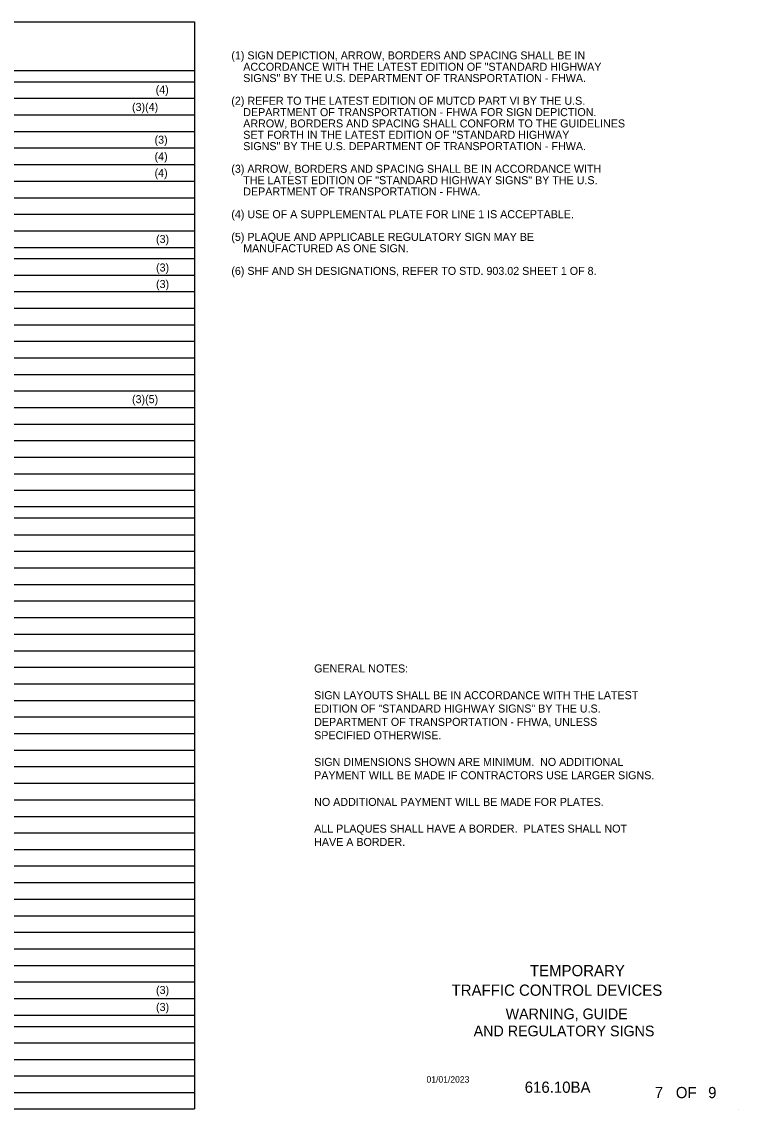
# Model space of a CAD drawing. Extents: x -439.1 to -407.9, y -458.1 to -437.7.
# Drawn here: x -421.29 to -407.86, y -458.05 to -437.68 of the extents above; entities that cross this region are included whole.
import ezdxf

# ---------------------------------------------------------------- set-up
doc = ezdxf.new("R2010")
doc.units = 0
for name, color, linetype in [('Common-Notes', 7, 'Continuous'), ('Level 4', 7, 'Continuous'), ('Level 45', 7, 'Continuous')]:
    doc.layers.add(name, color=color, linetype=linetype)

msp = doc.modelspace()

# ---------------------------------------------------------------- linework, layer by layer
at = {"layer": 'Common-Notes'}
msp.add_line((-439.109, -445.834), (-418.049, -445.834), dxfattribs=at)
at = {"layer": 'Level 4'}
for p, q in [((-439.109, -437.676), (-418.049, -437.676)), ((-418.049, -437.676), (-418.049, -458.044)), ((-439.109, -438.59), (-418.049, -438.59)), ((-439.109, -438.8), (-418.049, -438.8)), ((-439.109, -439.11), (-418.049, -439.11)), ((-439.109, -439.421), (-418.049, -439.421)), ((-439.109, -439.731), (-418.049, -439.731)), ((-439.109, -440.041), (-418.049, -440.041)), ((-439.109, -440.351), (-418.049, -440.351)), ((-439.109, -440.662), (-418.049, -440.662)), ((-439.109, -440.972), (-418.049, -440.972)), ((-439.109, -441.282), (-418.049, -441.282)), ((-439.109, -441.593), (-418.049, -441.593)), ((-439.109, -441.903), (-418.049, -441.903)), ((-439.109, -442.11), (-418.049, -442.11)), ((-439.109, -442.421), (-418.049, -442.421)), ((-439.109, -442.731), (-418.049, -442.731)), ((-439.109, -443.041), (-418.049, -443.041)), ((-439.109, -443.352), (-418.049, -443.352)), ((-439.109, -443.662), (-418.049, -443.662)), ((-439.109, -443.972), (-418.049, -443.972)), ((-439.109, -444.283), (-418.049, -444.283)), ((-439.109, -444.593), (-418.049, -444.593)), ((-439.109, -444.903), (-418.049, -444.903)), ((-418.762, -444.903), (-418.763, -444.903)), ((-439.109, -445.214), (-418.049, -445.214)), ((-439.109, -445.524), (-418.049, -445.524)), ((-439.109, -446.145), (-418.049, -446.145)), ((-439.109, -446.455), (-418.049, -446.455)), ((-418.049, -446.765), (-439.109, -446.765)), ((-418.049, -446.977), (-439.109, -446.977)), ((-439.109, -447.287), (-418.049, -447.287)), ((-439.109, -447.597), (-418.049, -447.597)), ((-439.109, -447.908), (-418.049, -447.908)), ((-439.109, -448.218), (-418.049, -448.218)), ((-439.109, -448.528), (-418.049, -448.528)), ((-439.109, -448.839), (-418.049, -448.839)), ((-439.109, -449.149), (-418.049, -449.149)), ((-439.109, -449.459), (-418.049, -449.459)), ((-439.109, -449.77), (-418.049, -449.77)), ((-439.109, -450.08), (-418.049, -450.08)), ((-439.109, -450.39), (-418.049, -450.39)), ((-439.109, -450.701), (-418.049, -450.701)), ((-439.109, -451.011), (-418.049, -451.011)), ((-439.109, -451.321), (-418.049, -451.321)), ((-439.109, -451.632), (-418.049, -451.632)), ((-439.109, -451.942), (-418.049, -451.942)), ((-439.109, -452.252), (-418.049, -452.252)), ((-439.109, -452.563), (-418.049, -452.563)), ((-439.109, -452.873), (-418.049, -452.873)), ((-439.109, -453.183), (-418.049, -453.183)), ((-439.109, -453.493), (-418.049, -453.493)), ((-439.109, -453.804), (-418.049, -453.804)), ((-439.109, -454.114), (-418.049, -454.114)), ((-439.109, -454.424), (-418.049, -454.424)), ((-439.109, -454.735), (-418.049, -454.735)), ((-439.109, -455.045), (-418.049, -455.045)), ((-439.109, -455.355), (-418.049, -455.355)), ((-439.109, -455.666), (-418.049, -455.666)), ((-439.109, -455.976), (-418.049, -455.976)), ((-439.109, -456.286), (-418.049, -456.286)), ((-439.109, -456.498), (-418.049, -456.498)), ((-439.109, -456.808), (-418.049, -456.808)), ((-439.109, -457.118), (-418.049, -457.118)), ((-439.109, -457.424), (-418.049, -457.424)), ((-439.109, -457.735), (-418.049, -457.735)), ((-439.109, -458.044), (-418.049, -458.044)), ((-407.859, -458.051), (-407.859, -458.051))]:
    msp.add_line(p, q, dxfattribs=at)

# ---------------------------------------------------------------- texts
at = {"layer": 'Common-Notes'}
for s, p in [('TEMPORARY', (-411.763, -455.558)), ('TRAFFIC CONTROL DEVICES', (-413.231, -455.925)), ('616.10BA', (-411.861, -457.743)), ('7', (-409.424, -457.843)), ('OF', (-409.029, -457.843)), ('9', (-408.424, -457.843))]:
    msp.add_text(s, height=0.21, dxfattribs=at).set_placement(p)
at = {"layer": 'Level 4'}
for s, height, p in [('(1) SIGN DEPICTION, ARROW, BORDERS AND SPACING SHALL BE IN ', 0.15, (-417.359, -438.381)), ('    ACCORDANCE WITH THE LATEST EDITION OF "STANDARD HIGHWAY ', 0.15, (-417.359, -438.594)), ('    SIGNS" BY THE U.S. DEPARTMENT OF TRANSPORTATION - FHWA.', 0.15, (-417.359, -438.806)), ('(4)', 0.15, (-418.777, -439.021)), ('(2) REFER TO THE LATEST EDITION OF MUTCD PART VI BY THE U.S. ', 0.15, (-417.359, -439.231)), ('(3)(4)', 0.15, (-419.22, -439.347)), ('    DEPARTMENT OF TRANSPORTATION - FHWA FOR SIGN DEPICTION. ', 0.15, (-417.359, -439.444)), ('    ARROW, BORDERS AND SPACING SHALL CONFORM TO THE GUIDELINES ', 0.15, (-417.359, -439.656)), ('(3)', 0.15, (-418.798, -439.961)), ('    SET FORTH IN THE LATEST EDITION OF "STANDARD HIGHWAY ', 0.15, (-417.359, -439.869)), ('    SIGNS" BY THE U.S. DEPARTMENT OF TRANSPORTATION - FHWA.', 0.15, (-417.359, -440.081)), ('(4)', 0.15, (-418.798, -440.272)), ('(4)', 0.15, (-418.798, -440.582)), ('(3) ARROW, BORDERS AND SPACING SHALL BE IN ACCORDANCE WITH ', 0.15, (-417.359, -440.506)), ('    THE LATEST EDITION OF "STANDARD HIGHWAY SIGNS" BY THE U.S. ', 0.15, (-417.359, -440.719)), ('    DEPARTMENT OF TRANSPORTATION - FHWA.', 0.15, (-417.359, -440.931)), ('(4) USE OF A SUPPLEMENTAL PLATE FOR LINE 1 IS ACCEPTABLE.', 0.15, (-417.359, -441.356)), ('(3)', 0.15, (-418.77, -441.821)), ('(5) PLAQUE AND APPLICABLE REGULATORY SIGN MAY BE ', 0.15, (-417.359, -441.781)), ('    MANUFACTURED AS ONE SIGN.', 0.15, (-417.359, -441.994)), ('(3)', 0.15, (-418.77, -442.355)), ('(6) SHF AND SH DESIGNATIONS, REFER TO STD. 903.02 SHEET 1 OF 8.', 0.15, (-417.359, -442.419)), ('(3)', 0.15, (-418.77, -442.665)), ('(3)(5)', 0.15, (-419.22, -444.822)), ('(3)', 0.15, (-418.77, -455.891)), ('(3)', 0.15, (-418.77, -456.209)), ('WARNING, GUIDE', 0.2, (-412.218, -456.364)), ('AND REGULATORY SIGNS', 0.2, (-412.818, -456.684)), ('01/01/2023', 0.12, (-413.701, -457.552))]:
    msp.add_text(s, height=height, dxfattribs=at).set_placement(p)
at = {"layer": 'Level 45'}
for s, p in [('GENERAL NOTES:', (-415.807, -449.868)), ('SIGN LAYOUTS SHALL BE IN ACCORDANCE WITH THE LATEST ', (-415.807, -450.368)), ('EDITION OF "STANDARD HIGHWAY SIGNS" BY THE U.S. ', (-415.807, -450.618)), ('DEPARTMENT OF TRANSPORTATION - FHWA, UNLESS ', (-415.807, -450.868)), ('SPECIFIED OTHERWISE.', (-415.807, -451.118)), ('SIGN DIMENSIONS SHOWN ARE MINIMUM.  NO ADDITIONAL ', (-415.807, -451.618)), ('PAYMENT WILL BE MADE IF CONTRACTORS USE LARGER SIGNS.', (-415.807, -451.868)), ('NO ADDITIONAL PAYMENT WILL BE MADE FOR PLATES. ', (-415.807, -452.368)), ('ALL PLAQUES SHALL HAVE A BORDER.  PLATES SHALL NOT ', (-415.807, -452.868)), ('HAVE A BORDER.', (-415.807, -453.118))]:
    msp.add_text(s, height=0.15, dxfattribs=at).set_placement(p)

doc.saveas('drawing.dxf')
